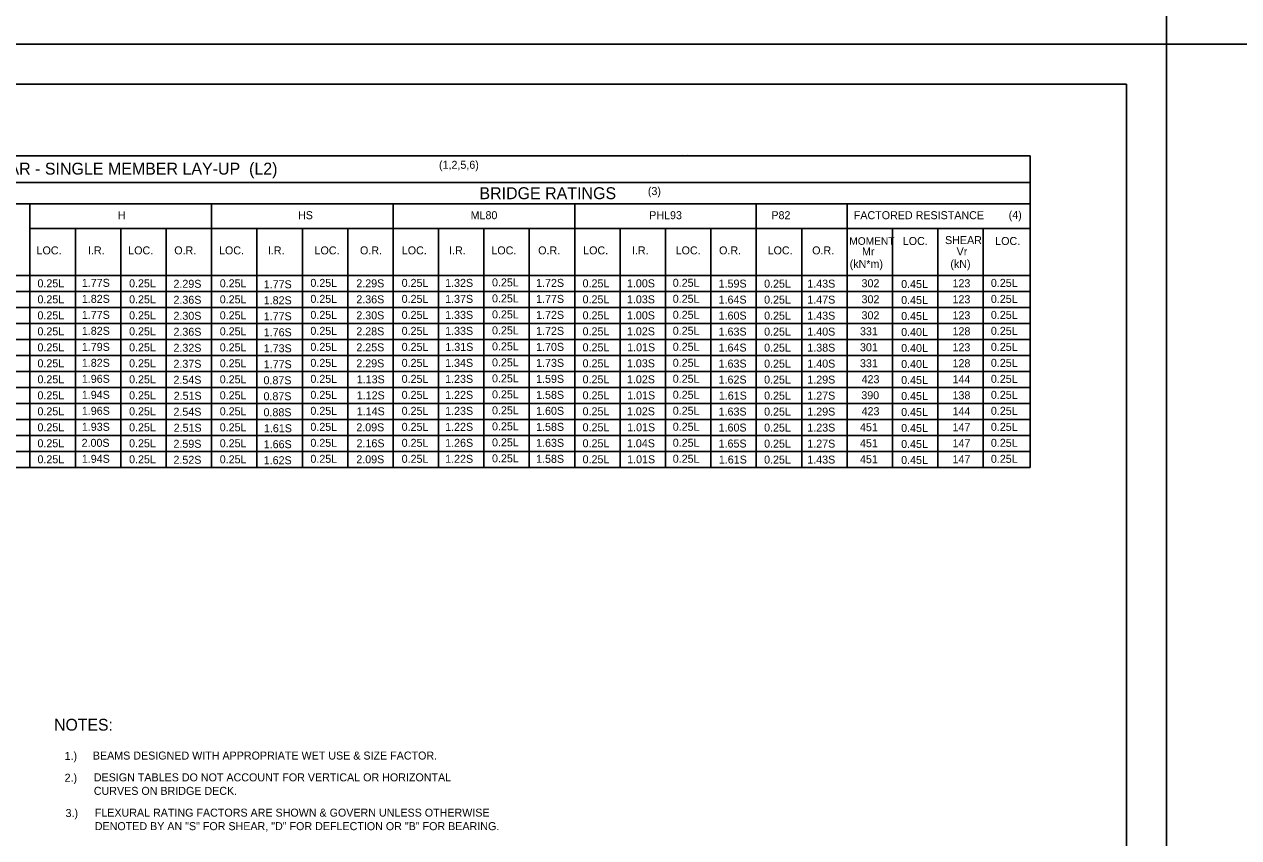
# Model space of a CAD drawing. Extents: x -5022 to -159, y 1126 to 7226.
# Drawn here: x -4268.3 to -3813, y 3204.2 to 3509.3 of the extents above; entities that cross this region are included whole.
import ezdxf

# ---------------------------------------------------------------- set-up
doc = ezdxf.new("R2010")
doc.units = 0
for name, color, linetype in [('2', 7, 'Continuous'), ('3', 7, 'Continuous'), ('PLT-BNDY', 7, 'Continuous')]:
    doc.layers.add(name, color=color, linetype=linetype)

msp = doc.modelspace()

# ---------------------------------------------------------------- linework, layer by layer
at = {"layer": '2'}
for q in [(-4641.13, 3486.81), (-3855.13, 2922.81)]:
    msp.add_line((-3855.13, 3486.81), q, dxfattribs=at)
at = {"layer": '3'}
for p, q in [((-4021.45, 3460.4), (-4021.45, 3460.4)), ((-4019.59, 3460.4), (-4019.59, 3460.4)), ((-4605.48, 3459.9), (-3891.16, 3459.9)), ((-3891.16, 3459.9), (-3891.16, 3343.1)), ((-4605.48, 3449.98), (-3891.16, 3449.98)), ((-4605.48, 3441.91), (-3891.16, 3441.91)), ((-4266.2, 3441.91), (-4266.2, 3343.1)), ((-4198.12, 3441.91), (-4198.12, 3343.1)), ((-4130.03, 3441.91), (-4130.03, 3343.1)), ((-4061.95, 3441.91), (-4061.95, 3343.1)), ((-3993.87, 3441.91), (-3993.87, 3343.1)), ((-3959.83, 3441.91), (-3959.83, 3343.1)), ((-4266.2, 3432.7), (-3891.16, 3432.7)), ((-4249.18, 3432.7), (-4249.18, 3343.1)), ((-4232.16, 3432.7), (-4232.16, 3343.1)), ((-4232.15, 3432.7), (-4232.15, 3343.1)), ((-4215.14, 3432.7), (-4215.14, 3343.1)), ((-4198.12, 3432.7), (-4198.12, 3343.1)), ((-4181.09, 3432.7), (-4181.09, 3343.1)), ((-4164.07, 3432.7), (-4164.07, 3343.1)), ((-4164.07, 3432.7), (-4164.07, 3343.1)), ((-4147.05, 3432.7), (-4147.05, 3343.1)), ((-4130.03, 3432.7), (-4130.03, 3343.1)), ((-4113.01, 3432.7), (-4113.01, 3343.1)), ((-4095.99, 3432.7), (-4095.99, 3343.1)), ((-4095.99, 3432.7), (-4095.99, 3343.1)), ((-4078.97, 3432.7), (-4078.97, 3343.1)), ((-4061.95, 3432.7), (-4061.95, 3343.1)), ((-4044.93, 3432.7), (-4044.93, 3343.1)), ((-4027.91, 3432.7), (-4027.91, 3343.1)), ((-4027.91, 3432.7), (-4027.91, 3343.1)), ((-4010.89, 3432.7), (-4010.89, 3343.1)), ((-3993.87, 3432.7), (-3993.87, 3343.1)), ((-3976.85, 3432.7), (-3976.85, 3343.1)), ((-3942.8, 3432.7), (-3942.8, 3343.1)), ((-3925.78, 3432.7), (-3925.78, 3343.1)), ((-3908.76, 3432.7), (-3908.76, 3343.1)), ((-4605.48, 3415.1), (-3891.16, 3415.1)), ((-4588, 3409.1), (-3891.16, 3409.1)), ((-4588, 3403.1), (-3891.16, 3403.1)), ((-4605.48, 3397.1), (-3891.16, 3397.1)), ((-4588, 3391.1), (-3891.16, 3391.1)), ((-4588, 3385.1), (-3891.16, 3385.1)), ((-4605.48, 3379.09), (-3891.16, 3379.1)), ((-4588, 3373.09), (-3891.16, 3373.1)), ((-4588, 3367.1), (-3891.16, 3367.1)), ((-4605.48, 3361.1), (-3891.16, 3361.1)), ((-4588, 3355.1), (-3891.16, 3355.1)), ((-4588, 3349.1), (-3891.16, 3349.1)), ((-4605.48, 3343.1), (-3891.16, 3343.1))]:
    msp.add_line(p, q, dxfattribs=at)
at = {"layer": 'PLT-BNDY'}
for points in [[(-4681.13, 4095.81), (-3840.13, 4095.81), (-3840.13, 3501.81), (-4681.13, 3501.81)], [(-3840.13, 4095.81), (-2999.13, 4095.81), (-2999.13, 3501.81), (-3840.13, 3501.81)], [(-4681.13, 3501.81), (-3840.13, 3501.81), (-3840.13, 2907.81), (-4681.13, 2907.81)], [(-3840.13, 3501.81), (-2999.13, 3501.81), (-2999.13, 2907.81), (-3840.13, 2907.81)]]:
    msp.add_lwpolyline(points, close=True, dxfattribs=at)

# ---------------------------------------------------------------- texts
at = {"layer": '2'}
for s, height, p in [('TABLE 2b - YELLOW POPLAR - SINGLE MEMBER LAY-UP  (L2)', 4.4793, (-4349.48, 3452.91)), ('(1,2,5,6)', 3, (-4112.84, 3455.1)), ('BRIDGE RATINGS', 4.4793, (-4097.68, 3443.7)), ('(3)', 3, (-4034.53, 3445.24)), ('H', 3, (-4233.23, 3436.19)), ('HS', 3, (-4165.68, 3436.19)), ('ML80', 3, (-4100.98, 3436.19)), ('PHL93', 3, (-4034.02, 3436.19)), ('P82', 3, (-3988.22, 3436.19)), ('FACTORED RESISTANCE', 3.0001, (-3957.32, 3436.19)), ('(4)', 3, (-3899.25, 3436.29)), ('MOMENT', 2.85, (-3959.01, 3426.58)), ('LOC.', 3, (-3938.95, 3426.51)), ('SHEAR', 3, (-3923.11, 3426.85)), ('LOC.', 3, (-3904.31, 3426.51)), ('LOC.', 3, (-4263.72, 3422.99)), ('I.R.', 3, (-4244.43, 3422.99)), ('LOC.', 3, (-4229.35, 3422.99)), ('O.R.', 3, (-4212.09, 3422.99)), ('LOC.', 3, (-4195.31, 3422.99)), ('I.R.', 3, (-4177, 3422.99)), ('LOC.', 3, (-4159.5, 3422.99)), ('O.R.', 3, (-4142.45, 3422.99)), ('LOC.', 3, (-4126.77, 3422.99)), ('I.R.', 3, (-4109.05, 3422.99)), ('LOC.', 3, (-4093.2, 3422.99)), ('O.R.', 3, (-4075.65, 3422.99)), ('LOC.', 3, (-4058.78, 3422.99)), ('I.R.', 3, (-4040.5, 3422.99)), ('LOC.', 3, (-4024.11, 3422.99)), ('O.R.', 3, (-4007.82, 3422.99)), ('LOC.', 3, (-3989.63, 3422.99)), ('O.R.', 3, (-3972.93, 3422.99)), ('Mr', 3, (-3954.26, 3422.58)), ('Vr', 3, (-3918.77, 3422.58)), ('(kN*m)', 3, (-3958.86, 3417.93)), ('(kN)', 3, (-3921.12, 3417.93)), ('0.25L', 3, (-4263.38, 3410.63)), ('1.77S', 3, (-4246.74, 3410.81)), ('0.25L', 3, (-4229.03, 3410.63)), ('2.29S', 3, (-4212.4, 3410.46)), ('0.25L', 3, (-4195.04, 3410.63)), ('1.77S', 3, (-4178.55, 3410.28)), ('0.25L', 3, (-4161.05, 3410.8)), ('2.29S', 3, (-4143.84, 3410.63)), ('0.25L', 3, (-4126.84, 3410.8)), ('1.32S', 3, (-4110.53, 3410.8)), ('0.25L', 3, (-4092.96, 3410.98)), ('1.72S', 3, (-4076.43, 3410.8)), ('0.25L', 3, (-4059, 3410.63)), ('1.00S', 3, (-4042.37, 3410.63)), ('0.25L', 3, (-4025.2, 3410.84)), ('1.59S', 3, (-4008, 3410.53)), ('0.25L', 3, (-3990.95, 3410.52)), ('1.43S', 3, (-3974.75, 3410.52)), ('302', 3, (-3954.42, 3410.66)), ('0.45L', 3, (-3939.57, 3410.37)), ('123', 3, (-3920.31, 3410.66)), ('0.25L', 3, (-3905.93, 3410.8)), ('0.25L', 3, (-4263.38, 3404.63)), ('1.82S', 3, (-4246.74, 3404.81)), ('0.25L', 3, (-4229.03, 3404.63)), ('2.36S', 3, (-4212.4, 3404.46)), ('0.25L', 3, (-4195.04, 3404.63)), ('1.82S', 3, (-4178.55, 3404.28)), ('0.25L', 3, (-4161.05, 3404.8)), ('2.36S', 3, (-4143.84, 3404.63)), ('0.25L', 3, (-4126.84, 3404.8)), ('1.37S', 3, (-4110.53, 3404.8)), ('0.25L', 3, (-4092.96, 3404.98)), ('1.77S', 3, (-4076.43, 3404.8)), ('0.25L', 3, (-4059, 3404.63)), ('1.03S', 3, (-4042.37, 3404.63)), ('0.25L', 3, (-4025.2, 3404.84)), ('1.64S', 3, (-4008, 3404.53)), ('0.25L', 3, (-3990.95, 3404.52)), ('1.47S', 3, (-3974.75, 3404.52)), ('302', 3, (-3954.42, 3404.66)), ('0.45L', 3, (-3939.57, 3404.37)), ('123', 3, (-3920.31, 3404.66)), ('0.25L', 3, (-3905.93, 3404.8)), ('0.25L', 3, (-4263.38, 3398.63)), ('1.77S', 3, (-4246.74, 3398.81)), ('0.25L', 3, (-4229.03, 3398.63)), ('2.30S', 3, (-4212.4, 3398.46)), ('0.25L', 3, (-4195.04, 3398.63)), ('1.77S', 3, (-4178.55, 3398.28)), ('0.25L', 3, (-4161.05, 3398.8)), ('2.30S', 3, (-4143.84, 3398.63)), ('0.25L', 3, (-4126.84, 3398.8)), ('1.33S', 3, (-4110.53, 3398.8)), ('0.25L', 3, (-4092.96, 3398.98)), ('1.72S', 3, (-4076.43, 3398.8)), ('0.25L', 3, (-4059, 3398.63)), ('1.00S', 3, (-4042.37, 3398.63)), ('0.25L', 3, (-4025.2, 3398.84)), ('1.60S', 3, (-4008, 3398.53)), ('0.25L', 3, (-3990.95, 3398.52)), ('1.43S', 3, (-3974.75, 3398.52)), ('302', 3, (-3954.42, 3398.66)), ('0.45L', 3, (-3939.57, 3398.37)), ('123', 3, (-3920.31, 3398.66)), ('0.25L', 3, (-3905.93, 3398.8)), ('0.25L', 3, (-4263.38, 3392.63)), ('1.82S', 3, (-4246.74, 3392.81)), ('0.25L', 3, (-4229.03, 3392.63)), ('2.36S', 3, (-4212.4, 3392.46)), ('0.25L', 3, (-4195.04, 3392.63)), ('1.76S', 3, (-4178.55, 3392.28)), ('0.25L', 3, (-4161.05, 3392.8)), ('2.28S', 3, (-4143.84, 3392.63)), ('0.25L', 3, (-4126.84, 3392.8)), ('1.33S', 3, (-4110.53, 3392.8)), ('0.25L', 3, (-4092.96, 3392.98)), ('1.72S', 3, (-4076.43, 3392.8)), ('0.25L', 3, (-4059, 3392.63)), ('1.02S', 3, (-4042.37, 3392.63)), ('0.25L', 3, (-4025.2, 3392.84)), ('1.63S', 3, (-4008, 3392.53)), ('0.25L', 3, (-3990.95, 3392.52)), ('1.40S', 3, (-3974.75, 3392.52)), ('331', 3, (-3955, 3392.66)), ('0.40L', 3, (-3939.57, 3392.37)), ('128', 3, (-3920.31, 3392.66)), ('0.25L', 3, (-3905.93, 3392.8)), ('0.25L', 3, (-4263.38, 3386.63)), ('1.79S', 3, (-4246.74, 3386.8)), ('0.25L', 3, (-4229.03, 3386.63)), ('2.32S', 3, (-4212.4, 3386.46)), ('0.25L', 3, (-4195.04, 3386.63)), ('1.73S', 3, (-4178.55, 3386.28)), ('0.25L', 3, (-4161.05, 3386.8)), ('2.25S', 3, (-4143.84, 3386.63)), ('0.25L', 3, (-4126.84, 3386.8)), ('1.31S', 3, (-4110.45, 3386.8)), ('0.25L', 3, (-4092.96, 3386.98)), ('1.70S', 3, (-4076.43, 3386.8)), ('0.25L', 3, (-4059, 3386.63)), ('1.01S', 3, (-4042.29, 3386.63)), ('0.25L', 3, (-4025.2, 3386.84)), ('1.64S', 3, (-4008, 3386.53)), ('0.25L', 3, (-3990.95, 3386.52)), ('1.38S', 3, (-3974.75, 3386.52)), ('301', 3, (-3955, 3386.66)), ('0.40L', 3, (-3939.57, 3386.37)), ('123', 3, (-3920.31, 3386.66)), ('0.25L', 3, (-3905.93, 3386.8)), ('0.25L', 3, (-4263.38, 3380.63)), ('1.82S', 3, (-4246.74, 3380.81)), ('0.25L', 3, (-4229.03, 3380.63)), ('2.37S', 3, (-4212.4, 3380.45)), ('0.25L', 3, (-4195.04, 3380.63)), ('1.77S', 3, (-4178.55, 3380.28)), ('0.25L', 3, (-4161.05, 3380.8)), ('2.29S', 3, (-4143.84, 3380.63)), ('0.25L', 3, (-4126.84, 3380.8)), ('1.34S', 3, (-4110.53, 3380.8)), ('0.25L', 3, (-4092.96, 3380.98)), ('1.73S', 3, (-4076.43, 3380.8)), ('0.25L', 3, (-4059, 3380.63)), ('1.03S', 3, (-4042.37, 3380.63)), ('0.25L', 3, (-4025.2, 3380.84)), ('1.63S', 3, (-4008, 3380.53)), ('0.25L', 3, (-3990.95, 3380.52)), ('1.40S', 3, (-3974.75, 3380.52)), ('331', 3, (-3955, 3380.66)), ('0.40L', 3, (-3939.57, 3380.37)), ('128', 3, (-3920.31, 3380.66)), ('0.25L', 3, (-3905.93, 3380.8)), ('0.25L', 3, (-4263.38, 3374.63)), ('1.96S', 3, (-4246.74, 3374.81)), ('0.25L', 3, (-4229.03, 3374.63)), ('2.54S', 3, (-4212.4, 3374.45)), ('0.25L', 3, (-4195.04, 3374.63)), ('0.87S', 3, (-4178.63, 3374.28)), ('0.25L', 3, (-4161.05, 3374.8)), ('1.13S', 3, (-4143.67, 3374.63)), ('0.25L', 3, (-4126.84, 3374.8)), ('1.23S', 3, (-4110.53, 3374.8)), ('0.25L', 3, (-4092.96, 3374.98)), ('1.59S', 3, (-4076.43, 3374.8)), ('0.25L', 3, (-4059, 3374.63)), ('1.02S', 3, (-4042.37, 3374.63)), ('0.25L', 3, (-4025.2, 3374.84)), ('1.62S', 3, (-4008, 3374.53)), ('0.25L', 3, (-3990.95, 3374.52)), ('1.29S', 3, (-3974.75, 3374.52)), ('423', 3, (-3954.4, 3374.66)), ('0.45L', 3, (-3939.57, 3374.37)), ('144', 3, (-3920.3, 3374.66)), ('0.25L', 3, (-3905.93, 3374.8)), ('0.25L', 3, (-4263.38, 3368.63)), ('1.94S', 3, (-4246.74, 3368.81)), ('0.25L', 3, (-4229.03, 3368.63)), ('2.51S', 3, (-4212.31, 3368.46)), ('0.25L', 3, (-4195.04, 3368.63)), ('0.87S', 3, (-4178.63, 3368.28)), ('0.25L', 3, (-4161.05, 3368.8)), ('1.12S', 3, (-4143.67, 3368.63)), ('0.25L', 3, (-4126.84, 3368.8)), ('1.22S', 3, (-4110.53, 3368.8)), ('0.25L', 3, (-4092.96, 3368.98)), ('1.58S', 3, (-4076.43, 3368.8)), ('0.25L', 3, (-4059, 3368.63)), ('1.01S', 3, (-4042.29, 3368.63)), ('0.25L', 3, (-4025.2, 3368.84)), ('1.61S', 3, (-4007.92, 3368.53)), ('0.25L', 3, (-3990.95, 3368.52)), ('1.27S', 3, (-3974.75, 3368.52)), ('390', 3, (-3954.51, 3368.66)), ('0.45L', 3, (-3939.57, 3368.37)), ('138', 3, (-3920.31, 3368.66)), ('0.25L', 3, (-3905.93, 3368.8)), ('0.25L', 3, (-4263.38, 3362.63)), ('1.96S', 3, (-4246.74, 3362.81)), ('0.25L', 3, (-4229.03, 3362.63)), ('2.54S', 3, (-4212.4, 3362.46)), ('0.25L', 3, (-4195.04, 3362.63)), ('0.88S', 3, (-4178.63, 3362.28)), ('0.25L', 3, (-4161.05, 3362.8)), ('1.14S', 3, (-4143.67, 3362.63)), ('0.25L', 3, (-4126.84, 3362.8)), ('1.23S', 3, (-4110.53, 3362.8)), ('0.25L', 3, (-4092.96, 3362.98)), ('1.60S', 3, (-4076.43, 3362.8)), ('0.25L', 3, (-4059, 3362.63)), ('1.02S', 3, (-4042.37, 3362.63)), ('0.25L', 3, (-4025.2, 3362.84)), ('1.63S', 3, (-4008, 3362.53)), ('0.25L', 3, (-3990.95, 3362.52)), ('1.29S', 3, (-3974.75, 3362.52)), ('423', 3, (-3954.4, 3362.66)), ('0.45L', 3, (-3939.57, 3362.37)), ('144', 3, (-3920.3, 3362.66)), ('0.25L', 3, (-3905.93, 3362.8)), ('0.25L', 3, (-4263.38, 3356.63)), ('1.93S', 3, (-4246.74, 3356.81)), ('0.25L', 3, (-4229.03, 3356.63)), ('2.51S', 3, (-4212.31, 3356.46)), ('0.25L', 3, (-4195.04, 3356.63)), ('1.61S', 3, (-4178.47, 3356.28)), ('0.25L', 3, (-4161.05, 3356.8)), ('2.09S', 3, (-4143.84, 3356.63)), ('0.25L', 3, (-4126.84, 3356.8)), ('1.22S', 3, (-4110.53, 3356.8)), ('0.25L', 3, (-4092.96, 3356.98)), ('1.58S', 3, (-4076.43, 3356.8)), ('0.25L', 3, (-4059, 3356.63)), ('1.01S', 3, (-4042.29, 3356.63)), ('0.25L', 3, (-4025.2, 3356.84)), ('1.60S', 3, (-4008, 3356.53)), ('0.25L', 3, (-3990.95, 3356.52)), ('1.23S', 3, (-3974.75, 3356.52)), ('451', 3, (-3955, 3356.66)), ('0.45L', 3, (-3939.57, 3356.37)), ('147', 3, (-3920.31, 3356.66)), ('0.25L', 3, (-3905.93, 3356.8)), ('0.25L', 3, (-4263.38, 3350.63)), ('2.00S', 3, (-4246.83, 3350.8)), ('0.25L', 3, (-4229.03, 3350.63)), ('2.59S', 3, (-4212.4, 3350.45)), ('0.25L', 3, (-4195.04, 3350.63)), ('1.66S', 3, (-4178.55, 3350.28)), ('0.25L', 3, (-4161.05, 3350.8)), ('2.16S', 3, (-4143.75, 3350.63)), ('0.25L', 3, (-4126.84, 3350.8)), ('1.26S', 3, (-4110.53, 3350.8)), ('0.25L', 3, (-4092.96, 3350.98)), ('1.63S', 3, (-4076.43, 3350.8)), ('0.25L', 3, (-4059, 3350.63)), ('1.04S', 3, (-4042.37, 3350.63)), ('0.25L', 3, (-4025.2, 3350.84)), ('1.65S', 3, (-4008, 3350.53)), ('0.25L', 3, (-3990.95, 3350.51)), ('1.27S', 3, (-3974.75, 3350.51)), ('451', 3, (-3955, 3350.66)), ('0.45L', 3, (-3939.57, 3350.37)), ('147', 3, (-3920.31, 3350.66)), ('0.25L', 3, (-3905.93, 3350.8)), ('0.25L', 3, (-4263.38, 3344.63)), ('1.94S', 3, (-4246.74, 3344.81)), ('0.25L', 3, (-4229.03, 3344.63)), ('2.52S', 3, (-4212.4, 3344.45)), ('0.25L', 3, (-4195.04, 3344.63)), ('1.62S', 3, (-4178.55, 3344.28)), ('0.25L', 3, (-4161.05, 3344.8)), ('2.09S', 3, (-4143.84, 3344.63)), ('0.25L', 3, (-4126.84, 3344.8)), ('1.22S', 3, (-4110.53, 3344.8)), ('0.25L', 3, (-4092.96, 3344.98)), ('1.58S', 3, (-4076.43, 3344.8)), ('0.25L', 3, (-4059, 3344.63)), ('1.01S', 3, (-4042.29, 3344.63)), ('0.25L', 3, (-4025.2, 3344.84)), ('1.61S', 3, (-4007.92, 3344.53)), ('0.25L', 3, (-3990.95, 3344.51)), ('1.43S', 3, (-3974.75, 3344.51)), ('451', 3, (-3955, 3344.66)), ('0.45L', 3, (-3939.57, 3344.37)), ('147', 3, (-3920.31, 3344.66)), ('0.25L', 3, (-3905.93, 3344.8)), ('NOTES:', 4.429, (-4257.14, 3244.35)), ('1.)', 3, (-4253.2, 3233.36)), ('BEAMS DESIGNED WITH APPROPRIATE WET USE & SIZE FACTOR.', 3.0001, (-4242.61, 3233.49)), ('2.)', 3, (-4253.2, 3225.18)), ('DESIGN TABLES DO NOT ACCOUNT FOR VERTICAL OR HORIZONTAL', 3.0001, (-4242.25, 3225.32)), ('CURVES ON BRIDGE DECK.', 3.0001, (-4242.25, 3220.25)), ('3.)', 3, (-4252.84, 3211.94)), ('FLEXURAL RATING FACTORS ARE SHOWN & GOVERN UNLESS OTHERWISE', 3.0001, (-4241.89, 3212.08)), ('DENOTED BY AN "S" FOR SHEAR, "D" FOR DEFLECTION OR "B" FOR BEARING.', 3.0001, (-4241.89, 3207.01))]:
    msp.add_text(s, height=height, dxfattribs=at).set_placement(p)

doc.saveas('drawing.dxf')
